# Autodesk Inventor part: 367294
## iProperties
Created: 2006-06
Part Number: 367294
Document SubType Name: Modeling
Designer: I.Baliuc
Material: 8.8 vz
Description: Sperrzahnschraube
Density: 7.85 g/cm^3
Mass: 14.7552 g
Surface Area: 10.8869 cm^2
Volume: 1.87964 cm^3
Abmessung: M8 x 12
Author: T.Messerschmitt
Revision Number: 367294
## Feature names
1. Basis1
